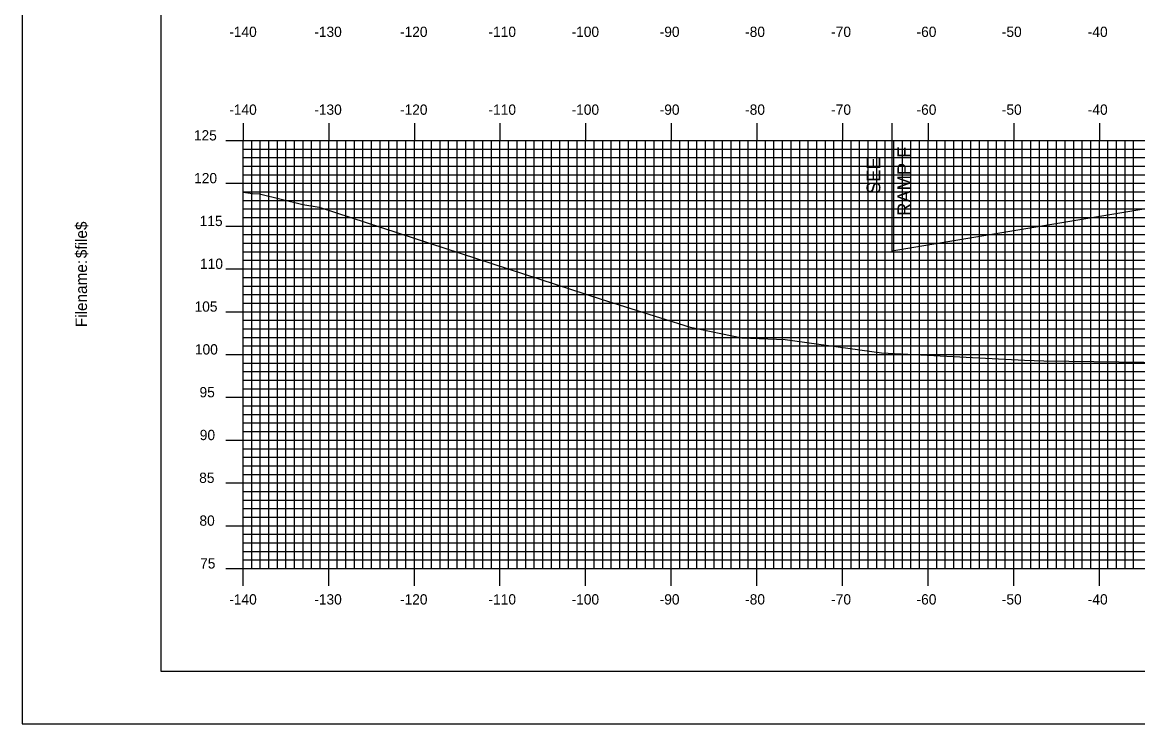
# Model space of a CAD drawing. Extents: x 856478 to 856821, y 364366 to 364586.
# Drawn here: x 856477.5 to 856607.8, y 364365.7 to 364447.6 of the extents above; entities that cross this region are included whole.
import ezdxf

# ---------------------------------------------------------------- set-up
doc = ezdxf.new("R2010")
doc.units = 0
for name, color, linetype in [('ANNOTATION', 7, 'Continuous'), ('BORDER', 7, 'Continuous'), ('D_Roadway_SlopeLines', 7, 'Continuous'), ('D_Roadway_SubGrade', 7, 'Continuous'), ('H_V ANNOTATION', 7, 'Continuous'), ('MAJOR', 7, 'Continuous'), ('MINOR', 7, 'Continuous'), ('PLOT BOUNDARY', 7, 'Continuous'), ('S_Roadway_Centerline', 7, 'Continuous')]:
    doc.layers.add(name, color=color, linetype=linetype)

msp = doc.modelspace()

# ---------------------------------------------------------------- linework, layer by layer
at = {"layer": 'BORDER'}
msp.add_lwpolyline([(856493.71, 364371.79), (856813.71, 364371.79), (856813.71, 364581.79), (856493.71, 364581.79)], close=True, dxfattribs=at)
at = {"layer": 'D_Roadway_SlopeLines'}
msp.add_lwpolyline([(856625.31, 364428.56), (856579.07, 364420.86)], dxfattribs=at)
at = {"layer": 'D_Roadway_SubGrade'}
msp.add_line((856579.07, 364435.81), (856579.07, 364420.86), dxfattribs=at)
at = {"layer": 'MAJOR'}
for p, q in [((856503.31, 364435.79), (856503.31, 364433.79)), ((856513.31, 364435.79), (856513.31, 364433.79)), ((856523.31, 364435.79), (856523.31, 364433.79)), ((856533.31, 364435.79), (856533.31, 364433.79)), ((856543.31, 364435.79), (856543.31, 364433.79)), ((856553.31, 364435.79), (856553.31, 364433.79)), ((856563.31, 364435.79), (856563.31, 364433.79)), ((856573.31, 364435.79), (856573.31, 364433.79)), ((856583.31, 364435.79), (856583.31, 364433.79)), ((856593.31, 364435.79), (856593.31, 364433.79)), ((856603.31, 364435.79), (856603.31, 364433.79)), ((856501.31, 364433.79), (856503.31, 364433.79)), ((856503.31, 364433.79), (856783.31, 364433.79)), ((856503.31, 364383.79), (856503.31, 364433.79)), ((856503.31, 364383.79), (856503.31, 364433.79)), ((856503.31, 364433.79), (856783.31, 364433.79)), ((856513.31, 364383.79), (856513.31, 364433.79)), ((856523.31, 364383.79), (856523.31, 364433.79)), ((856533.31, 364383.79), (856533.31, 364433.79)), ((856543.31, 364383.79), (856543.31, 364433.79)), ((856553.31, 364383.79), (856553.31, 364433.79)), ((856563.31, 364383.79), (856563.31, 364433.79)), ((856573.31, 364383.79), (856573.31, 364433.79)), ((856583.31, 364383.79), (856583.31, 364433.79)), ((856593.31, 364383.79), (856593.31, 364433.79)), ((856603.31, 364383.79), (856603.31, 364433.79)), ((856501.31, 364428.79), (856503.31, 364428.79)), ((856503.31, 364428.79), (856783.31, 364428.79)), ((856501.31, 364423.79), (856503.31, 364423.79)), ((856503.31, 364423.79), (856783.31, 364423.79)), ((856501.31, 364418.79), (856503.31, 364418.79)), ((856503.31, 364418.79), (856783.31, 364418.79)), ((856501.31, 364413.79), (856503.31, 364413.79)), ((856503.31, 364413.79), (856783.31, 364413.79)), ((856501.31, 364408.79), (856503.31, 364408.79)), ((856503.31, 364408.79), (856783.31, 364408.79)), ((856501.31, 364403.79), (856503.31, 364403.79)), ((856503.31, 364403.79), (856783.31, 364403.79)), ((856501.31, 364398.79), (856503.31, 364398.79)), ((856503.31, 364398.79), (856783.31, 364398.79)), ((856501.31, 364393.79), (856503.31, 364393.79)), ((856503.31, 364393.79), (856783.31, 364393.79)), ((856501.31, 364388.79), (856503.31, 364388.79)), ((856503.31, 364388.79), (856783.31, 364388.79)), ((856501.31, 364383.79), (856503.31, 364383.79)), ((856503.31, 364383.79), (856783.31, 364383.79)), ((856503.31, 364383.79), (856783.31, 364383.79)), ((856503.31, 364381.78), (856503.31, 364383.79)), ((856513.31, 364381.78), (856513.31, 364383.79)), ((856523.31, 364381.78), (856523.31, 364383.79)), ((856533.31, 364381.78), (856533.31, 364383.79)), ((856543.31, 364381.78), (856543.31, 364383.79)), ((856553.31, 364381.78), (856553.31, 364383.79)), ((856563.31, 364381.78), (856563.31, 364383.79)), ((856573.31, 364381.78), (856573.31, 364383.79)), ((856583.31, 364381.78), (856583.31, 364383.79)), ((856593.31, 364381.78), (856593.31, 364383.79)), ((856603.31, 364381.78), (856603.31, 364383.79))]:
    msp.add_line(p, q, dxfattribs=at)
at = {"layer": 'MINOR'}
for p, q in [((856504.31, 364383.79), (856504.31, 364433.79)), ((856505.31, 364383.79), (856505.31, 364433.79)), ((856506.31, 364383.79), (856506.31, 364433.79)), ((856507.31, 364383.79), (856507.31, 364433.79)), ((856508.31, 364383.79), (856508.31, 364433.79)), ((856509.31, 364383.79), (856509.31, 364433.79)), ((856510.31, 364383.79), (856510.31, 364433.79)), ((856511.31, 364383.79), (856511.31, 364433.79)), ((856512.31, 364383.79), (856512.31, 364433.79)), ((856514.31, 364383.79), (856514.31, 364433.79)), ((856515.31, 364383.79), (856515.31, 364433.79)), ((856516.31, 364383.79), (856516.31, 364433.79)), ((856517.31, 364383.79), (856517.31, 364433.79)), ((856518.31, 364383.79), (856518.31, 364433.79)), ((856519.31, 364383.79), (856519.31, 364433.79)), ((856520.31, 364383.79), (856520.31, 364433.79)), ((856521.31, 364383.79), (856521.31, 364433.79)), ((856522.31, 364383.79), (856522.31, 364433.79)), ((856524.31, 364383.79), (856524.31, 364433.79)), ((856525.31, 364383.79), (856525.31, 364433.79)), ((856526.31, 364383.79), (856526.31, 364433.79)), ((856527.31, 364383.79), (856527.31, 364433.79)), ((856528.31, 364383.79), (856528.31, 364433.79)), ((856529.31, 364383.79), (856529.31, 364433.79)), ((856530.31, 364383.79), (856530.31, 364433.79)), ((856531.31, 364383.79), (856531.31, 364433.79)), ((856532.31, 364383.79), (856532.31, 364433.79)), ((856534.31, 364383.79), (856534.31, 364433.79)), ((856535.31, 364383.79), (856535.31, 364433.79)), ((856536.31, 364383.79), (856536.31, 364433.79)), ((856537.31, 364383.79), (856537.31, 364433.79)), ((856538.31, 364383.79), (856538.31, 364433.79)), ((856539.31, 364383.79), (856539.31, 364433.79)), ((856540.31, 364383.79), (856540.31, 364433.79)), ((856541.31, 364383.79), (856541.31, 364433.79)), ((856542.31, 364383.79), (856542.31, 364433.79)), ((856544.31, 364383.79), (856544.31, 364433.79)), ((856545.31, 364383.79), (856545.31, 364433.79)), ((856546.31, 364383.79), (856546.31, 364433.79)), ((856547.31, 364383.79), (856547.31, 364433.79)), ((856548.31, 364383.79), (856548.31, 364433.79)), ((856549.31, 364383.79), (856549.31, 364433.79)), ((856550.31, 364383.79), (856550.31, 364433.79)), ((856551.31, 364383.79), (856551.31, 364433.79)), ((856552.31, 364383.79), (856552.31, 364433.79)), ((856554.31, 364383.79), (856554.31, 364433.79)), ((856555.31, 364383.79), (856555.31, 364433.79)), ((856556.31, 364383.79), (856556.31, 364433.79)), ((856557.31, 364383.79), (856557.31, 364433.79)), ((856558.31, 364383.79), (856558.31, 364433.79)), ((856559.31, 364383.79), (856559.31, 364433.79)), ((856560.31, 364383.79), (856560.31, 364433.79)), ((856561.31, 364383.79), (856561.31, 364433.79)), ((856562.31, 364383.79), (856562.31, 364433.79)), ((856564.31, 364383.79), (856564.31, 364433.79)), ((856565.31, 364383.79), (856565.31, 364433.79)), ((856566.31, 364383.79), (856566.31, 364433.79)), ((856567.31, 364383.79), (856567.31, 364433.79)), ((856568.31, 364383.79), (856568.31, 364433.79)), ((856569.31, 364383.79), (856569.31, 364433.79)), ((856570.31, 364383.79), (856570.31, 364433.79)), ((856571.31, 364383.79), (856571.31, 364433.79)), ((856572.31, 364383.79), (856572.31, 364433.79)), ((856574.31, 364383.79), (856574.31, 364433.79)), ((856575.31, 364383.79), (856575.31, 364433.79)), ((856576.31, 364383.79), (856576.31, 364433.79)), ((856577.31, 364383.79), (856577.31, 364433.79)), ((856578.31, 364383.79), (856578.31, 364433.79)), ((856579.31, 364383.79), (856579.31, 364433.79)), ((856580.31, 364383.79), (856580.31, 364433.79)), ((856581.31, 364383.79), (856581.31, 364433.79)), ((856582.31, 364383.79), (856582.31, 364433.79)), ((856584.31, 364383.79), (856584.31, 364433.79)), ((856585.31, 364383.79), (856585.31, 364433.79)), ((856586.31, 364383.79), (856586.31, 364433.79)), ((856587.31, 364383.79), (856587.31, 364433.79)), ((856588.31, 364383.79), (856588.31, 364433.79)), ((856589.31, 364383.79), (856589.31, 364433.79)), ((856590.31, 364383.79), (856590.31, 364433.79)), ((856591.31, 364383.79), (856591.31, 364433.79)), ((856592.31, 364383.79), (856592.31, 364433.79)), ((856594.31, 364383.79), (856594.31, 364433.79)), ((856595.31, 364383.79), (856595.31, 364433.79)), ((856596.31, 364383.79), (856596.31, 364433.79)), ((856597.31, 364383.79), (856597.31, 364433.79)), ((856598.31, 364383.79), (856598.31, 364433.79)), ((856599.31, 364383.79), (856599.31, 364433.79)), ((856600.31, 364383.79), (856600.31, 364433.79)), ((856601.31, 364383.79), (856601.31, 364433.79)), ((856602.31, 364383.79), (856602.31, 364433.79)), ((856604.31, 364383.79), (856604.31, 364433.79)), ((856605.31, 364383.79), (856605.31, 364433.79)), ((856606.31, 364383.79), (856606.31, 364433.79)), ((856607.31, 364383.79), (856607.31, 364433.79)), ((856503.31, 364432.79), (856783.31, 364432.79)), ((856503.31, 364432.79), (856505.31, 364432.79)), ((856503.31, 364431.79), (856783.31, 364431.79)), ((856503.31, 364431.79), (856505.31, 364431.79)), ((856503.31, 364430.79), (856783.31, 364430.79)), ((856503.31, 364430.79), (856505.31, 364430.79)), ((856503.31, 364429.79), (856783.31, 364429.79)), ((856503.31, 364429.79), (856505.31, 364429.79)), ((856503.31, 364427.79), (856783.31, 364427.79)), ((856503.31, 364427.79), (856505.31, 364427.79)), ((856503.31, 364426.79), (856783.31, 364426.79)), ((856503.31, 364426.79), (856505.31, 364426.79)), ((856503.31, 364425.79), (856783.31, 364425.79)), ((856503.31, 364425.79), (856505.31, 364425.79)), ((856503.31, 364424.79), (856783.31, 364424.79)), ((856503.31, 364424.79), (856505.31, 364424.79)), ((856503.31, 364422.79), (856783.31, 364422.79)), ((856503.31, 364422.79), (856505.31, 364422.79)), ((856503.31, 364421.79), (856783.31, 364421.79)), ((856503.31, 364421.79), (856505.31, 364421.79)), ((856503.31, 364420.79), (856783.31, 364420.79)), ((856503.31, 364420.79), (856505.31, 364420.79)), ((856503.31, 364419.79), (856783.31, 364419.79)), ((856503.31, 364419.79), (856505.31, 364419.79)), ((856503.31, 364417.79), (856783.31, 364417.79)), ((856503.31, 364417.79), (856505.31, 364417.79)), ((856503.31, 364416.79), (856783.31, 364416.79)), ((856503.31, 364416.79), (856505.31, 364416.79)), ((856503.31, 364415.79), (856783.31, 364415.79)), ((856503.31, 364415.79), (856505.31, 364415.79)), ((856503.31, 364414.79), (856783.31, 364414.79)), ((856503.31, 364414.79), (856505.31, 364414.79)), ((856503.31, 364412.79), (856783.31, 364412.79)), ((856503.31, 364412.79), (856505.31, 364412.79)), ((856503.31, 364411.79), (856783.31, 364411.79)), ((856503.31, 364411.79), (856505.31, 364411.79)), ((856503.31, 364410.79), (856783.31, 364410.79)), ((856503.31, 364410.79), (856505.31, 364410.79)), ((856503.31, 364409.79), (856783.31, 364409.79)), ((856503.31, 364409.79), (856505.31, 364409.79)), ((856503.31, 364407.79), (856783.31, 364407.79)), ((856503.31, 364407.79), (856505.31, 364407.79)), ((856503.31, 364406.79), (856783.31, 364406.79)), ((856503.31, 364406.79), (856505.31, 364406.79)), ((856503.31, 364405.79), (856783.31, 364405.79)), ((856503.31, 364405.79), (856505.31, 364405.79)), ((856503.31, 364404.79), (856783.31, 364404.79)), ((856503.31, 364404.79), (856505.31, 364404.79)), ((856503.31, 364402.79), (856783.31, 364402.79)), ((856503.31, 364402.79), (856505.31, 364402.79)), ((856503.31, 364401.79), (856783.31, 364401.79)), ((856503.31, 364401.79), (856505.31, 364401.79)), ((856503.31, 364400.79), (856783.31, 364400.79)), ((856503.31, 364400.79), (856505.31, 364400.79)), ((856503.31, 364399.79), (856783.31, 364399.79)), ((856503.31, 364399.79), (856505.31, 364399.79)), ((856503.31, 364397.79), (856783.31, 364397.79)), ((856503.31, 364397.79), (856505.31, 364397.79)), ((856503.31, 364396.79), (856783.31, 364396.79)), ((856503.31, 364396.79), (856505.31, 364396.79)), ((856503.31, 364395.79), (856783.31, 364395.79)), ((856503.31, 364395.79), (856505.31, 364395.79)), ((856503.31, 364394.79), (856783.31, 364394.79)), ((856503.31, 364394.79), (856505.31, 364394.79)), ((856503.31, 364392.79), (856783.31, 364392.79)), ((856503.31, 364392.79), (856505.31, 364392.79)), ((856503.31, 364391.79), (856783.31, 364391.79)), ((856503.31, 364391.79), (856505.31, 364391.79)), ((856503.31, 364390.79), (856783.31, 364390.79)), ((856503.31, 364390.79), (856505.31, 364390.79)), ((856503.31, 364389.79), (856783.31, 364389.79)), ((856503.31, 364389.79), (856505.31, 364389.79)), ((856503.31, 364387.79), (856783.31, 364387.79)), ((856503.31, 364387.79), (856505.31, 364387.79)), ((856503.31, 364386.79), (856783.31, 364386.79)), ((856503.31, 364386.79), (856505.31, 364386.79)), ((856503.31, 364385.79), (856783.31, 364385.79)), ((856503.31, 364385.79), (856505.31, 364385.79)), ((856503.31, 364384.79), (856783.31, 364384.79)), ((856503.31, 364384.79), (856505.31, 364384.79))]:
    msp.add_line(p, q, dxfattribs=at)
at = {"layer": 'PLOT BOUNDARY'}
msp.add_lwpolyline([(856477.52, 364365.67), (856817.52, 364365.67), (856817.52, 364585.67), (856477.52, 364585.67)], close=True, dxfattribs=at)
at = {"layer": 'S_Roadway_Centerline'}
msp.add_lwpolyline([(856503.31, 364427.76), (856504.4, 364427.61), (856505.23, 364427.56), (856510.28, 364426.31), (856512.21, 364425.99), (856539.74, 364416.99), (856545.13, 364415.26), (856555.52, 364411.97), (856561.54, 364410.73), (856566.63, 364410.55), (856577.87, 364408.97), (856580.96, 364408.84), (856594.55, 364408.11), (856596.81, 364408.06), (856611.41, 364407.86)], dxfattribs=at)

# ---------------------------------------------------------------- texts
at = {"layer": 'ANNOTATION'}
for s, p in [('RAMP F', (856581.33, 364424.99)), ('SEE', (856577.73, 364427.54))]:
    msp.add_text(s, height=1.6, rotation=90, dxfattribs=at).set_placement(p)
at = {"layer": 'BORDER'}
for s, p in [('$file$', (856485.08, 364420.04)), ('Filename:', (856485.08, 364411.98))]:
    msp.add_text(s, height=1.339, rotation=90, dxfattribs=at).set_placement(p)
at = {"layer": 'H_V ANNOTATION'}
for s, p in [('-140', (856501.69, 364445.88)), ('-130', (856511.62, 364445.88)), ('-120', (856521.63, 364445.88)), ('-110', (856531.97, 364445.88)), ('-100', (856541.67, 364445.88)), ('-90', (856551.96, 364445.88)), ('-80', (856561.94, 364445.88)), ('-70', (856571.99, 364445.88)), ('-60', (856581.96, 364445.88)), ('-50', (856591.92, 364445.88)), ('-40', (856601.96, 364445.88)), ('-140', (856501.69, 364436.79)), ('-130', (856511.62, 364436.79)), ('-120', (856521.63, 364436.79)), ('-110', (856531.97, 364436.79)), ('-100', (856541.67, 364436.79)), ('-90', (856551.96, 364436.79)), ('-80', (856561.94, 364436.79)), ('-70', (856571.99, 364436.79)), ('-60', (856581.96, 364436.79)), ('-50', (856591.92, 364436.79)), ('-40', (856601.96, 364436.79)), ('125', (856497.56, 364433.79)), ('120', (856497.59, 364428.79)), ('115', (856498.24, 364423.79)), ('110', (856498.28, 364418.79)), ('105', (856497.64, 364413.79)), ('100', (856497.68, 364408.79)), ('95', (856498.22, 364403.79)), ('90', (856498.25, 364398.79)), ('85', (856498.18, 364393.79)), ('80', (856498.21, 364388.79)), ('75', (856498.29, 364383.79)), ('-140', (856501.69, 364379.59)), ('-130', (856511.62, 364379.59)), ('-120', (856521.63, 364379.59)), ('-110', (856531.97, 364379.59)), ('-100', (856541.67, 364379.59)), ('-90', (856551.96, 364379.59)), ('-80', (856561.94, 364379.59)), ('-70', (856571.99, 364379.59)), ('-60', (856581.96, 364379.59)), ('-50', (856591.92, 364379.59)), ('-40', (856601.96, 364379.59))]:
    msp.add_text(s, height=1.2, dxfattribs=at).set_placement(p)
at = {"layer": 'MAJOR'}
msp.add_text('-', height=0.012, dxfattribs=at).set_placement((856503.3, 364383.79))

doc.saveas('drawing.dxf')
